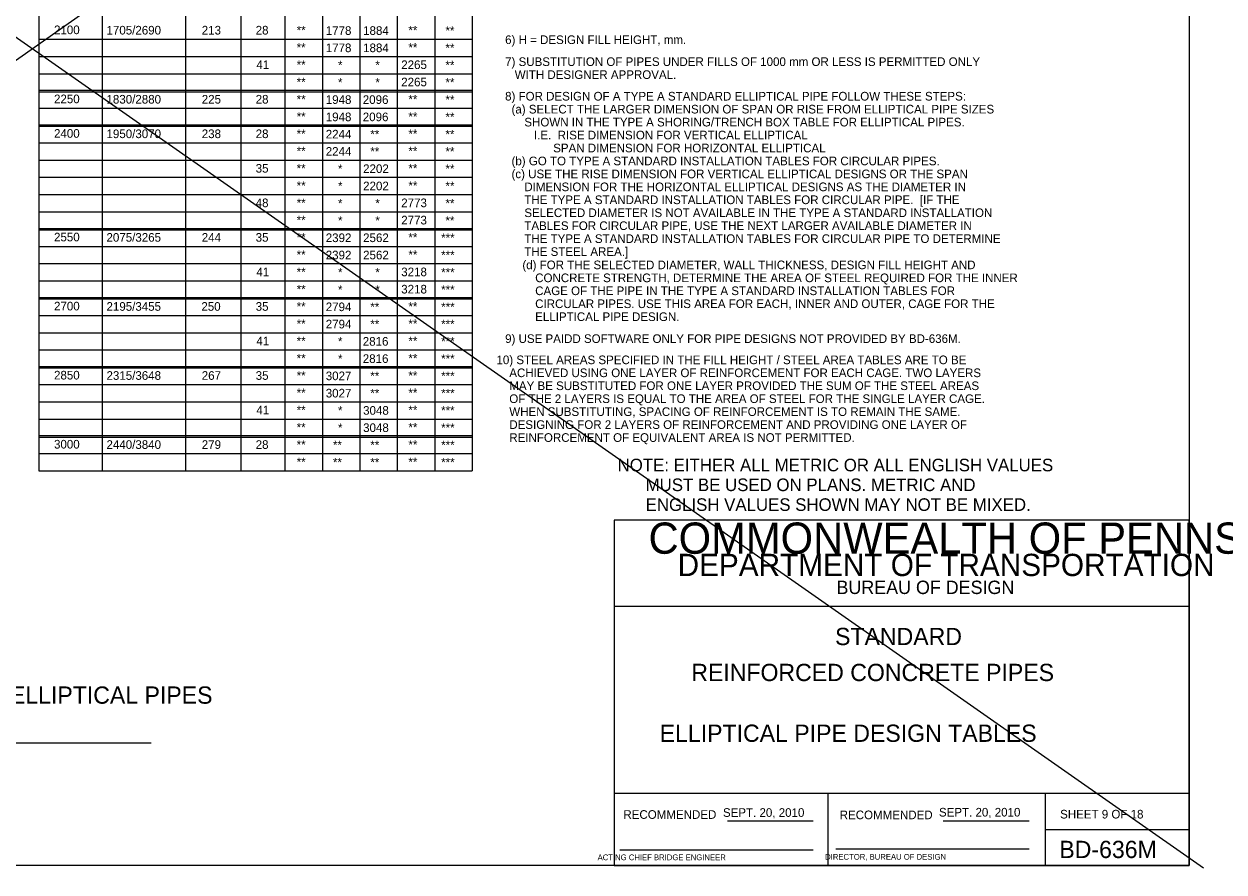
# Model space of a CAD drawing. Extents: x -22562 to -18409, y 3991 to 7171.
# Drawn here: x -20805 to -20387.7, y 4598.2 to 4892.8 of the extents above; entities that cross this region are included whole.
import ezdxf

# ---------------------------------------------------------------- set-up
doc = ezdxf.new("R2010")
doc.units = 0
doc.layers.add('2', color=7, linetype='Continuous')
doc.layers.add('Default', color=7, linetype='Continuous')

msp = doc.modelspace()

# ---------------------------------------------------------------- linework, layer by layer
at = {"layer": '2'}
for p, q in [((-20399.85, 5164.37), (-20399.85, 4600.37)), ((-20799.85, 5151.68), (-20799.85, 4737.55)), ((-20649.22, 5151.68), (-20649.22, 4737.55)), ((-20714.35, 5140.12), (-20714.35, 4737.55)), ((-20777.85, 5129.3), (-20777.85, 4737.55)), ((-20748.85, 5129.3), (-20748.85, 4737.55)), ((-20729.6, 5129.3), (-20729.6, 4737.55)), ((-20701.22, 5129.3), (-20701.22, 4737.55)), ((-20688.22, 5129.3), (-20688.22, 4737.55)), ((-20675.22, 5129.3), (-20675.22, 4737.55)), ((-20662.22, 5129.3), (-20662.22, 4737.55)), ((-20799.85, 4887.55), (-20649.22, 4887.55)), ((-20799.85, 4881.55), (-20649.22, 4881.55)), ((-20799.85, 4875.55), (-20649.22, 4875.55)), ((-20799.85, 4869.8), (-20649.22, 4869.8)), ((-20799.85, 4869.3), (-20649.22, 4869.3)), ((-20799.85, 4863.55), (-20649.22, 4863.55)), ((-20799.85, 4857.8), (-20649.22, 4857.8)), ((-20799.85, 4857.3), (-20649.22, 4857.3)), ((-20799.85, 4851.55), (-20649.22, 4851.55)), ((-20799.85, 4845.55), (-20649.22, 4845.55)), ((-20799.85, 4839.55), (-20649.22, 4839.55)), ((-20799.85, 4833.55), (-20649.22, 4833.55)), ((-20799.85, 4827.55), (-20649.22, 4827.55)), ((-20799.85, 4821.8), (-20649.22, 4821.8)), ((-20799.85, 4821.3), (-20649.22, 4821.3)), ((-20799.85, 4815.55), (-20649.22, 4815.55)), ((-20799.85, 4809.55), (-20649.22, 4809.55)), ((-20799.85, 4803.55), (-20649.22, 4803.55)), ((-20799.85, 4797.8), (-20649.22, 4797.8)), ((-20799.85, 4797.3), (-20649.22, 4797.3)), ((-20799.85, 4791.55), (-20649.22, 4791.55)), ((-20799.85, 4785.55), (-20649.22, 4785.55)), ((-20799.85, 4779.55), (-20649.22, 4779.55)), ((-20799.85, 4773.8), (-20649.22, 4773.8)), ((-20799.85, 4773.3), (-20649.22, 4773.3)), ((-20799.85, 4767.55), (-20649.22, 4767.55)), ((-20799.85, 4761.55), (-20649.22, 4761.55)), ((-20799.85, 4755.55), (-20649.22, 4755.55)), ((-20799.85, 4749.8), (-20649.22, 4749.8)), ((-20799.85, 4749.3), (-20649.22, 4749.3)), ((-20799.85, 4743.55), (-20649.22, 4743.55)), ((-20799.85, 4737.55), (-20649.22, 4737.55)), ((-20399.85, 4720.37), (-20599.85, 4720.37)), ((-20599.85, 4720.37), (-20599.85, 4600.37)), ((-20399.85, 4600.37), (-20399.85, 4720.37)), ((-20399.85, 4690.37), (-20599.85, 4690.37)), ((-20996.85, 4642.99), (-20760.85, 4642.99)), ((-20399.85, 4625.37), (-20599.85, 4625.37)), ((-20525.35, 4600.37), (-20525.35, 4625.37)), ((-20449.85, 4625.37), (-20449.85, 4600.37)), ((-20560.38, 4615.87), (-20530.62, 4615.87)), ((-20485.38, 4615.87), (-20455.47, 4615.87)), ((-20449.85, 4612.87), (-20399.85, 4612.87)), ((-20597.85, 4605.87), (-20530.62, 4605.87)), ((-20522.72, 4606.24), (-20455.47, 4606.24)), ((-20399.85, 4600.37), (-21185.85, 4600.37)), ((-20599.85, 4600.37), (-20399.85, 4600.37))]:
    msp.add_line(p, q, dxfattribs=at)
at = {"layer": 'Default'}
for p, q in [((-21209.2, 4598.15), (-20392, 5172.65)), ((-21210.63, 5169.78), (-20394.86, 4599.58))]:
    msp.add_line(p, q, dxfattribs=at)

# ---------------------------------------------------------------- texts
at = {"layer": '2'}
for s, height, p in [('2100', 3, (-20794.6, 4889.3)), ('1705/2690', 3, (-20776.35, 4889.18)), ('213', 3, (-20743.22, 4889.18)), ('28', 3, (-20724.47, 4889.18)), ('**', 3, (-20710.22, 4889.18)), ('1778', 3, (-20700.1, 4889.05)), ('1884', 3, (-20687.1, 4889.05)), ('**', 3, (-20671.35, 4889.18)), ('**', 3, (-20658.47, 4889.05)), ('6) H = DESIGN FILL HEIGHT, mm.', 3, (-20637.72, 4885.87)), ('**', 3, (-20710.22, 4883.18)), ('1778', 3, (-20700.1, 4883.05)), ('1884', 3, (-20687.1, 4883.05)), ('**', 3, (-20671.35, 4883.18)), ('**', 3, (-20658.47, 4883.05)), ('41', 3, (-20724.22, 4877.18)), ('**', 3, (-20710.22, 4877.18)), ('*', 3, (-20695.85, 4877.05)), ('*', 3, (-20682.85, 4877.05)), ('2265', 3, (-20673.85, 4877.18)), ('**', 3, (-20658.47, 4877.05)), ('7) SUBSTITUTION OF PIPES UNDER FILLS OF 1000 mm OR LESS IS PERMITTED ONLY', 3, (-20637.72, 4878.24)), ('   WITH DESIGNER APPROVAL.', 3, (-20637.72, 4873.74)), ('**', 3, (-20710.22, 4871.18)), ('*', 3, (-20695.85, 4871.05)), ('*', 3, (-20682.85, 4871.05)), ('2265', 3, (-20673.85, 4871.18)), ('**', 3, (-20658.47, 4871.05)), ('2250', 3, (-20794.6, 4865.3)), ('1830/2880', 3, (-20776.35, 4865.18)), ('225', 3, (-20743.22, 4865.18)), ('28', 3, (-20724.47, 4865.18)), ('**', 3, (-20710.22, 4865.18)), ('1948', 3, (-20700.1, 4865.05)), ('2096', 3, (-20687.22, 4865.05)), ('**', 3, (-20671.35, 4865.18)), ('**', 3, (-20658.47, 4865.05)), ('8) FOR DESIGN OF A TYPE A STANDARD ELLIPTICAL PIPE FOLLOW THESE STEPS:', 3, (-20637.72, 4866.24)), ('**', 3, (-20710.22, 4859.18)), ('1948', 3, (-20700.1, 4859.05)), ('2096', 3, (-20687.22, 4859.05)), ('**', 3, (-20671.35, 4859.18)), ('**', 3, (-20658.47, 4859.05)), ('  (a) SELECT THE LARGER DIMENSION OF SPAN OR RISE FROM ELLIPTICAL PIPE SIZES', 3, (-20637.72, 4861.74)), ('      SHOWN IN THE TYPE A SHORING/TRENCH BOX TABLE FOR ELLIPTICAL PIPES.', 3, (-20637.72, 4857.24)), ('2400', 3, (-20794.6, 4853.3)), ('1950/3070', 3, (-20776.35, 4853.18)), ('238', 3, (-20743.22, 4853.18)), ('28', 3, (-20724.47, 4853.18)), ('**', 3, (-20710.22, 4853.18)), ('2244', 3, (-20700.1, 4853.05)), ('**', 3, (-20684.6, 4853.05)), ('**', 3, (-20671.35, 4853.18)), ('**', 3, (-20658.47, 4853.05)), ('         I.E.  RISE DIMENSION FOR VERTICAL ELLIPTICAL', 3, (-20637.72, 4852.74)), ('**', 3, (-20710.22, 4847.18)), ('2244', 3, (-20700.1, 4847.05)), ('**', 3, (-20684.6, 4847.05)), ('**', 3, (-20671.35, 4847.18)), ('**', 3, (-20658.47, 4847.05)), ('               SPAN DIMENSION FOR HORIZONTAL ELLIPTICAL', 3, (-20637.72, 4848.24)), ('  (b) GO TO TYPE A STANDARD INSTALLATION TABLES FOR CIRCULAR PIPES.', 3, (-20637.72, 4843.74)), ('35', 3, (-20724.47, 4841.18)), ('**', 3, (-20710.22, 4841.18)), ('*', 3, (-20695.85, 4841.05)), ('2202', 3, (-20687.1, 4841.05)), ('**', 3, (-20671.35, 4841.18)), ('**', 3, (-20658.47, 4841.05)), ('  (c) USE THE RISE DIMENSION FOR VERTICAL ELLIPTICAL DESIGNS OR THE SPAN', 3, (-20637.72, 4839.24)), ('**', 3, (-20710.22, 4835.18)), ('*', 3, (-20695.85, 4835.05)), ('2202', 3, (-20687.1, 4835.05)), ('**', 3, (-20671.35, 4835.18)), ('**', 3, (-20658.47, 4835.05)), ('      DIMENSION FOR THE HORIZONTAL ELLIPTICAL DESIGNS AS THE DIAMETER IN', 3, (-20637.72, 4834.74)), ('      THE TYPE A STANDARD INSTALLATION TABLES FOR CIRCULAR PIPE.  [IF THE', 3, (-20637.72, 4830.24)), ('48', 3, (-20724.47, 4829.18)), ('**', 3, (-20710.22, 4829.18)), ('*', 3, (-20695.85, 4829.05)), ('*', 3, (-20682.85, 4829.05)), ('2773', 3, (-20673.85, 4829.18)), ('**', 3, (-20658.47, 4829.05)), ('      SELECTED DIAMETER IS NOT AVAILABLE IN THE TYPE A STANDARD INSTALLATION', 3, (-20637.72, 4825.74)), ('**', 3, (-20710.22, 4823.18)), ('*', 3, (-20695.85, 4823.05)), ('*', 3, (-20682.85, 4823.05)), ('2773', 3, (-20673.85, 4823.18)), ('**', 3, (-20658.47, 4823.05)), ('2550', 3, (-20794.6, 4817.3)), ('2075/3265', 3, (-20776.35, 4817.18)), ('244', 3, (-20743.22, 4817.18)), ('35', 3, (-20724.47, 4817.18)), ('      TABLES FOR CIRCULAR PIPE, USE THE NEXT LARGER AVAILABLE DIAMETER IN', 3, (-20637.72, 4821.24)), ('**', 3, (-20710.22, 4817.18)), ('2392', 3, (-20700.1, 4817.05)), ('2562', 3, (-20687.1, 4817.05)), ('**', 3, (-20671.35, 4817.18)), ('***', 3, (-20659.97, 4817.05)), ('      THE TYPE A STANDARD INSTALLATION TABLES FOR CIRCULAR PIPE TO DETERMINE', 3, (-20637.72, 4816.74)), ('**', 3, (-20710.22, 4811.18)), ('2392', 3, (-20700.1, 4811.05)), ('2562', 3, (-20687.1, 4811.05)), ('**', 3, (-20671.35, 4811.18)), ('***', 3, (-20659.97, 4811.05)), ('      THE STEEL AREA.]', 3, (-20637.72, 4812.24)), ('41', 3, (-20724.22, 4805.18)), ('**', 3, (-20710.22, 4805.18)), ('*', 3, (-20695.85, 4805.05)), ('*', 3, (-20682.85, 4805.05)), ('3218', 3, (-20673.85, 4805.18)), ('***', 3, (-20659.97, 4805.05)), ('(d) FOR THE SELECTED DIAMETER, WALL THICKNESS, DESIGN FILL HEIGHT AND', 3, (-20631.72, 4807.62)), ('    CONCRETE STRENGTH, DETERMINE THE AREA OF STEEL REQUIRED FOR THE INNER', 3, (-20631.72, 4803.12)), ('**', 3, (-20710.22, 4799.18)), ('*', 3, (-20695.85, 4799.05)), ('*', 3, (-20682.85, 4799.05)), ('3218', 3, (-20673.85, 4799.18)), ('***', 3, (-20659.97, 4799.05)), ('    CAGE OF THE PIPE IN THE TYPE A STANDARD INSTALLATION TABLES FOR', 3, (-20631.72, 4798.62)), ('2700', 3, (-20794.6, 4793.3)), ('2195/3455', 3, (-20776.35, 4793.18)), ('250', 3, (-20743.35, 4793.18)), ('35', 3, (-20724.47, 4793.18)), ('**', 3, (-20710.22, 4793.18)), ('2794', 3, (-20700.1, 4793.05)), ('**', 3, (-20684.6, 4793.05)), ('**', 3, (-20671.35, 4793.18)), ('***', 3, (-20659.97, 4793.05)), ('    CIRCULAR PIPES. USE THIS AREA FOR EACH, INNER AND OUTER, CAGE FOR THE', 3, (-20631.72, 4794.12)), ('    ELLIPTICAL PIPE DESIGN.', 3, (-20631.72, 4789.62)), ('**', 3, (-20710.22, 4787.18)), ('2794', 3, (-20700.1, 4787.05)), ('**', 3, (-20684.6, 4787.05)), ('**', 3, (-20671.35, 4787.18)), ('***', 3, (-20659.97, 4787.05)), ('41', 3, (-20724.22, 4781.18)), ('**', 3, (-20710.22, 4781.18)), ('*', 3, (-20695.85, 4781.05)), ('2816', 3, (-20687.22, 4781.05)), ('**', 3, (-20671.35, 4781.18)), ('***', 3, (-20659.97, 4781.05)), ('9) USE PAIDD SOFTWARE ONLY FOR PIPE DESIGNS NOT PROVIDED BY BD-636M.', 3, (-20637.72, 4781.99)), ('**', 3, (-20710.22, 4775.18)), ('*', 3, (-20695.85, 4775.05)), ('2816', 3, (-20687.22, 4775.05)), ('**', 3, (-20671.35, 4775.18)), ('***', 3, (-20659.97, 4775.05)), ('10) STEEL AREAS SPECIFIED IN THE FILL HEIGHT / STEEL AREA TABLES ARE TO BE', 3, (-20640.72, 4774.62)), ('2850', 3, (-20794.6, 4769.3)), ('2315/3648', 3, (-20776.35, 4769.18)), ('267', 3, (-20743.22, 4769.18)), ('35', 3, (-20724.47, 4769.18)), ('**', 3, (-20710.22, 4769.18)), ('3027', 3, (-20700.1, 4769.05)), ('**', 3, (-20684.6, 4769.05)), ('**', 3, (-20671.35, 4769.18)), ('***', 3, (-20659.97, 4769.05)), ('    ACHIEVED USING ONE LAYER OF REINFORCEMENT FOR EACH CAGE. TWO LAYERS', 3, (-20640.72, 4770.12)), ('**', 3, (-20710.22, 4763.18)), ('3027', 3, (-20700.1, 4763.05)), ('**', 3, (-20684.6, 4763.05)), ('**', 3, (-20671.35, 4763.18)), ('***', 3, (-20659.97, 4763.05)), ('    MAY BE SUBSTITUTED FOR ONE LAYER PROVIDED THE SUM OF THE STEEL AREAS', 3, (-20640.72, 4765.62)), ('    OF THE 2 LAYERS IS EQUAL TO THE AREA OF STEEL FOR THE SINGLE LAYER CAGE.', 3, (-20640.72, 4761.12)), ('41', 3, (-20724.22, 4757.18)), ('**', 3, (-20710.22, 4757.18)), ('*', 3, (-20695.85, 4757.05)), ('3048', 3, (-20687.1, 4757.05)), ('**', 3, (-20671.35, 4757.18)), ('***', 3, (-20659.97, 4757.05)), ('    WHEN SUBSTITUTING, SPACING OF REINFORCEMENT IS TO REMAIN THE SAME.', 3, (-20640.72, 4756.62)), ('**', 3, (-20710.22, 4751.18)), ('*', 3, (-20695.85, 4751.05)), ('3048', 3, (-20687.1, 4751.05)), ('**', 3, (-20671.35, 4751.18)), ('***', 3, (-20659.97, 4751.05)), ('    DESIGNING FOR 2 LAYERS OF REINFORCEMENT AND PROVIDING ONE LAYER OF', 3, (-20640.72, 4752.12)), ('    REINFORCEMENT OF EQUIVALENT AREA IS NOT PERMITTED.', 3, (-20640.72, 4747.62)), ('3000', 3, (-20794.6, 4745.3)), ('2440/3840', 3, (-20776.35, 4745.18)), ('279', 3, (-20743.22, 4745.18)), ('28', 3, (-20724.47, 4745.18)), ('**', 3, (-20710.22, 4745.18)), ('**', 3, (-20697.6, 4745.05)), ('**', 3, (-20684.6, 4745.05)), ('**', 3, (-20671.35, 4745.18)), ('***', 3, (-20659.97, 4745.05)), ('**', 3, (-20710.22, 4739.18)), ('**', 3, (-20697.6, 4739.05)), ('**', 3, (-20684.6, 4739.05)), ('**', 3, (-20671.35, 4739.18)), ('***', 3, (-20659.97, 4739.05)), ('NOTE: EITHER ALL METRIC OR ALL ENGLISH VALUES', 4.375, (-20598.61, 4737.38)), ('      MUST BE USED ON PLANS. METRIC AND', 4.375, (-20598.61, 4730.51)), ('      ENGLISH VALUES SHOWN MAY NOT BE MIXED.', 4.375, (-20598.61, 4723.63)), ('COMMONWEALTH OF PENNSYLVANIA', 10.8525, (-20587.85, 4708.74)), ('DEPARTMENT OF TRANSPORTATION', 7.7332, (-20577.72, 4700.99)), ('BUREAU OF DESIGN', 4.6493, (-20522.47, 4694.74)), ('STANDARD', 6, (-20522.97, 4676.99)), ('REINFORCED CONCRETE PIPES', 6, (-20572.97, 4664.49)), ('DESIGN TABLES AND PROOF TEST LOAD TABLE FOR VERTICAL & HORIZONTAL ELLIPTICAL PIPES', 6, (-21122.47, 4656.62)), ('ELLIPTICAL PIPE DESIGN TABLES', 6, (-20583.97, 4643.37)), ('SEPT. 20, 2010', 3, (-20561.96, 4617.31)), ('SEPT. 20, 2010', 3, (-20486.84, 4617.42)), ('SHEET 9 OF 18', 3, (-20444.7, 4616.74)), ('BD-636M', 6, (-20444.97, 4602.99)), ('       ACTING CHIEF BRIDGE ENGINEER', 2.0002, (-20610.76, 4602.24))]:
    msp.add_text(s, height=height, dxfattribs=at).set_placement(p)
for s, height, p in [('RECOMMENDED', 3, (-20596.58, 4616.62)), ('RECOMMENDED', 3, (-20521.36, 4616.49)), ('   DIRECTOR, BUREAU OF DESIGN', 2.0002, (-20528.65, 4602.42))]:
    msp.add_text(s, height=height, rotation=360, dxfattribs=at).set_placement(p)

doc.saveas('drawing.dxf')
